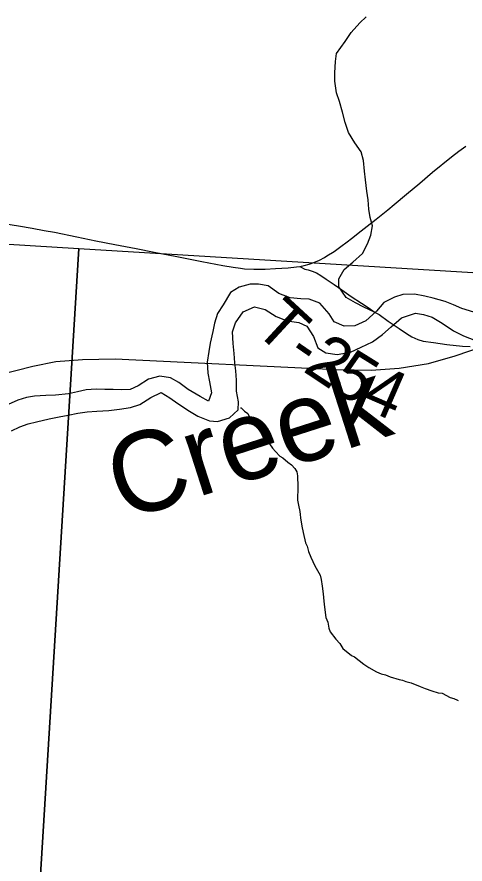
# Model space of a CAD drawing. Extents: x 0 to 44, y -23.8 to 22.
# Drawn here: x 5.49 to 6.018, y 18.843 to 19.842 of the extents above; entities that cross this region are included whole.
import ezdxf

# ---------------------------------------------------------------- set-up
doc = ezdxf.new("R2010")
doc.units = 0
for name, color, linetype in [('GM_X_County_Road', 7, 'Continuous'), ('GM_X_Minor_River', 7, 'Continuous'), ('GM_X_Minor_River_Text', 7, 'Continuous'), ('GM_X_Rail_Line', 7, 'Continuous'), ('GM_X_Section', 7, 'Continuous'), ('GM_X_State_Route', 7, 'Continuous'), ('GM_X_Township_Road', 7, 'Continuous'), ('GM_X_Township_Road_Text', 7, 'Continuous')]:
    doc.layers.add(name, color=color, linetype=linetype)

msp = doc.modelspace()

# ---------------------------------------------------------------- linework, layer by layer
at = {"layer": 'GM_X_County_Road'}
for points in [[(5.82345, 19.54806), (5.8288, 19.5492), (5.83469, 19.55073), (5.84009, 19.55248), (5.8467, 19.55539), (5.85252, 19.55854), (5.85553, 19.56027), (5.86384, 19.56572), (5.87173, 19.57129), (5.8792, 19.57687), (5.88428, 19.58084), (5.89568, 19.58986), (5.91338, 19.60362), (5.92709, 19.61457), (5.93474, 19.62103), (5.94909, 19.63306), (5.96502, 19.64634), (5.97989, 19.65898), (6.00211, 19.67726), (6.01089, 19.68402), (6.01908, 19.68984)], [(5.43885, 19.60412), (5.45669, 19.60149), (5.47469, 19.59878), (5.49187, 19.59598), (5.50807, 19.59319), (5.52196, 19.59047), (5.53414, 19.58841), (5.56078, 19.58299), (5.58312, 19.57835)], [(5.58312, 19.57835), (5.60546, 19.57371), (5.63052, 19.56898), (5.65173, 19.56484), (5.67856, 19.55971), (5.70785, 19.55389), (5.73291, 19.54925), (5.74494, 19.54698), (5.75353, 19.5458), (5.75834, 19.54518), (5.76928, 19.54469), (5.78251, 19.54493), (5.79476, 19.54559), (5.80972, 19.5465), (5.81967, 19.54748), (5.82345, 19.54806)]]:
    msp.add_lwpolyline(points, dxfattribs=at)
at = {"layer": 'GM_X_Minor_River'}
for points in [[(5.91219, 19.49362), (5.89914, 19.50008), (5.88932, 19.50508), (5.878, 19.51123), (5.86938, 19.52381), (5.86945, 19.53329), (5.87596, 19.54425), (5.88587, 19.55291), (5.8973, 19.56308), (5.90344, 19.5748), (5.9073, 19.58501), (5.90927, 19.596), (5.9063, 19.60551), (5.90485, 19.61539), (5.90417, 19.62639), (5.90235, 19.63665), (5.90093, 19.65032), (5.89986, 19.66019), (5.89843, 19.6731), (5.89585, 19.68299), (5.88835, 19.69366), (5.88086, 19.70586), (5.87678, 19.71765), (5.87383, 19.72981), (5.87013, 19.74274), (5.86679, 19.75262), (5.86462, 19.76668), (5.86468, 19.77654), (5.86553, 19.78982), (5.86674, 19.79929), (5.87706, 19.81326), (5.88395, 19.82384), (5.89425, 19.83553), (5.90187, 19.84231)], [(6.02864, 19.4939), (6.01458, 19.49847), (6.0047, 19.50266), (5.99482, 19.50647), (5.98076, 19.51066), (5.97088, 19.51295), (5.95872, 19.51524), (5.94504, 19.51487), (5.93516, 19.51184), (5.92261, 19.50539), (5.91386, 19.49513), (5.90131, 19.48374), (5.88838, 19.47804), (5.87584, 19.47729), (5.86406, 19.48262), (5.85799, 19.49213), (5.84697, 19.50469), (5.83443, 19.50926), (5.82455, 19.50965), (5.81201, 19.5108), (5.79871, 19.51613), (5.78617, 19.52489), (5.77477, 19.52718), (5.76489, 19.52718), (5.75197, 19.52339), (5.7417, 19.51732), (5.73295, 19.5025), (5.72648, 19.49224), (5.72305, 19.48122), (5.72076, 19.47134), (5.71771, 19.45728), (5.71619, 19.44778), (5.71428, 19.43485), (5.71503, 19.42193), (5.71692, 19.41166), (5.71957, 19.39874), (5.71577, 19.38886), (5.70589, 19.39457), (5.69183, 19.40294), (5.68082, 19.41093), (5.67094, 19.41664), (5.6584, 19.41855), (5.64509, 19.41476), (5.63292, 19.40717), (5.62342, 19.40262), (5.61316, 19.40225), (5.60365, 19.40263), (5.59377, 19.40264), (5.58351, 19.40303), (5.57173, 19.40228), (5.56146, 19.40001), (5.55082, 19.39774), (5.53562, 19.39623), (5.52421, 19.39586), (5.51091, 19.39473), (5.50141, 19.39322), (5.49114, 19.39018), (5.47974, 19.38525)], [(5.48347, 19.35396), (5.49335, 19.3589), (5.50324, 19.36231), (5.51312, 19.36458), (5.52795, 19.36799), (5.53973, 19.37064), (5.55037, 19.37253), (5.56178, 19.3748), (5.5728, 19.37631), (5.58421, 19.37706), (5.59827, 19.37781), (5.61081, 19.3797), (5.62374, 19.38159), (5.63476, 19.385), (5.64769, 19.39336), (5.66023, 19.39905), (5.67011, 19.39296), (5.67961, 19.38611), (5.69328, 19.37735), (5.70316, 19.37126), (5.71684, 19.36593), (5.72634, 19.36516), (5.74041, 19.36933), (5.75068, 19.37883), (5.75107, 19.38833), (5.74879, 19.40087), (5.7488, 19.4138), (5.74805, 19.42482), (5.74692, 19.43433), (5.74616, 19.44535), (5.74503, 19.45714), (5.74428, 19.47082), (5.74771, 19.48147), (5.75684, 19.49438), (5.77014, 19.50045), (5.78268, 19.49702), (5.7956, 19.48903), (5.80852, 19.4837), (5.8222, 19.48178), (5.8317, 19.47759), (5.83967, 19.46542), (5.84461, 19.45211), (5.8541, 19.44602), (5.8674, 19.44411), (5.88337, 19.44676), (5.89592, 19.45283), (5.90922, 19.4589), (5.92101, 19.46764), (5.93128, 19.47675), (5.94345, 19.48738), (5.9598, 19.49269), (5.9693, 19.49116), (5.97956, 19.48811), (5.99134, 19.48088), (6.00463, 19.47213), (6.01641, 19.46604), (6.03047, 19.4607)], [(5.7537, 19.38133), (5.75419, 19.38108), (5.75832, 19.37722), (5.76208, 19.37452), (5.76431, 19.37031), (5.76882, 19.36645), (5.77292, 19.3607), (5.77703, 19.35457), (5.78076, 19.3492), (5.78524, 19.34268), (5.78785, 19.33885), (5.7912, 19.33349), (5.79495, 19.32964), (5.79982, 19.32426), (5.80359, 19.32231), (5.80922, 19.31692), (5.81374, 19.31383), (5.81748, 19.3096), (5.82009, 19.30577), (5.82079, 19.30082), (5.82103, 19.2879), (5.82085, 19.27232), (5.82191, 19.26622), (5.82335, 19.25899), (5.82406, 19.25518), (5.8244, 19.25138), (5.8258, 19.24148), (5.82761, 19.23424), (5.83013, 19.22167), (5.83198, 19.21784), (5.8338, 19.21174), (5.83638, 19.20487), (5.84119, 19.19455), (5.84752, 19.18383), (5.84859, 19.17849), (5.85002, 19.17088), (5.85106, 19.16175), (5.85138, 19.15718), (5.85205, 19.14919), (5.85415, 19.13359), (5.85636, 19.12824), (5.85779, 19.121), (5.85926, 19.1168), (5.866, 19.10836), (5.87086, 19.10298), (5.87421, 19.09724), (5.88436, 19.08913), (5.88814, 19.08756), (5.89904, 19.07868), (5.90468, 19.07481), (5.91373, 19.06976), (5.91939, 19.0674), (5.92431, 19.0662), (5.92997, 19.06385), (5.94056, 19.06068), (5.94435, 19.05987), (5.9485, 19.0583), (5.95493, 19.05669), (5.9655, 19.05238), (5.97117, 19.05003), (5.9791, 19.04727), (5.98666, 19.04489), (5.99121, 19.04445), (6.00064, 19.0394), (6.00518, 19.0382), (6.00932, 19.03625), (6.00999, 19.03596)]]:
    msp.add_lwpolyline(points, dxfattribs=at)
at = {"layer": 'GM_X_Rail_Line'}
msp.add_lwpolyline([(5.46999, 19.42057), (5.5086, 19.43023), (5.53595, 19.43586), (5.56732, 19.43828), (5.60593, 19.43908), (5.86653, 19.4262), (5.90755, 19.42539), (5.94053, 19.42781), (5.97511, 19.43344), (6.00648, 19.44229), (6.04107, 19.45436)], dxfattribs=at)
at = {"layer": 'GM_X_Section'}
for points in [[(4.53628, 19.63237), (5.56281, 19.56926), (5.50086, 18.55371), (4.48532, 18.61908)], [(5.56281, 19.56926), (6.58215, 19.50692), (6.51337, 18.48797), (5.50086, 18.55371)]]:
    msp.add_lwpolyline(points, close=True, dxfattribs=at)
at = {"layer": 'GM_X_State_Route'}
for points in [[(5.82345, 19.54806), (5.8288, 19.5492), (5.83469, 19.55073), (5.84009, 19.55248), (5.8467, 19.55539), (5.85252, 19.55854), (5.85553, 19.56027), (5.86384, 19.56572), (5.87173, 19.57129), (5.8792, 19.57687), (5.88428, 19.58084), (5.89568, 19.58986), (5.91338, 19.60362), (5.92709, 19.61457), (5.93474, 19.62103), (5.94909, 19.63306), (5.96502, 19.64634), (5.97989, 19.65898), (6.00211, 19.67726), (6.01089, 19.68402), (6.01908, 19.68984)], [(5.43885, 19.60412), (5.45669, 19.60149), (5.47469, 19.59878), (5.49187, 19.59598), (5.50807, 19.59319), (5.52196, 19.59047), (5.53414, 19.58841), (5.56078, 19.58299), (5.58312, 19.57835)], [(5.58312, 19.57835), (5.60546, 19.57371), (5.63052, 19.56898), (5.65173, 19.56484), (5.67856, 19.55971), (5.70785, 19.55389), (5.73291, 19.54925), (5.74494, 19.54698), (5.75353, 19.5458), (5.75834, 19.54518), (5.76928, 19.54469), (5.78251, 19.54493), (5.79476, 19.54559), (5.80972, 19.5465), (5.81967, 19.54748), (5.82345, 19.54806)]]:
    msp.add_lwpolyline(points, dxfattribs=at)
at = {"layer": 'GM_X_Township_Road'}
for points in [[(5.43885, 19.60412), (5.45669, 19.60149), (5.47469, 19.59878), (5.49187, 19.59598), (5.50807, 19.59319), (5.52196, 19.59047), (5.53414, 19.58841), (5.56078, 19.58299), (5.58312, 19.57835)], [(5.58312, 19.57835), (5.60546, 19.57371), (5.63052, 19.56898), (5.65173, 19.56484), (5.67856, 19.55971), (5.70785, 19.55389), (5.73291, 19.54925), (5.74494, 19.54698), (5.75353, 19.5458), (5.75834, 19.54518), (5.76928, 19.54469), (5.78251, 19.54493), (5.79476, 19.54559), (5.80972, 19.5465), (5.81967, 19.54748), (5.82345, 19.54806)], [(5.82345, 19.54806), (5.82937, 19.54474), (5.83345, 19.54402), (5.83819, 19.54251), (5.84322, 19.54027), (5.84817, 19.53731), (5.85474, 19.53287), (5.86411, 19.52654), (5.87291, 19.5203), (5.88417, 19.51249), (5.89634, 19.50476), (5.90398, 19.49942), (5.91245, 19.49374), (5.91705, 19.4912), (5.92782, 19.48345), (5.94051, 19.47471), (5.94906, 19.46879), (5.95544, 19.46484), (5.96267, 19.46182), (5.96892, 19.45978), (5.98092, 19.45827), (5.99687, 19.45596), (6.01512, 19.45383), (6.02416, 19.45333)]]:
    msp.add_lwpolyline(points, dxfattribs=at)

# ---------------------------------------------------------------- texts
at = {"layer": 'GM_X_Minor_River_Text'}
msp.add_text('Creek', height=0.094693, rotation=17.79903, dxfattribs=at).set_placement((5.615, 19.24729))
at = {"layer": 'GM_X_Township_Road_Text'}
for s, rotation, p in [('T', 317.26578, (5.76753, 19.47332)), ('2', 326.44676, (5.82575, 19.4251)), ('-', 325.38252, (5.80559, 19.439)), ('5', 328.0685, (5.85639, 19.40481)), ('4', 336.50547, (5.89416, 19.38206))]:
    msp.add_text(s, height=0.05682, rotation=rotation, dxfattribs=at).set_placement(p)

doc.saveas('drawing.dxf')
